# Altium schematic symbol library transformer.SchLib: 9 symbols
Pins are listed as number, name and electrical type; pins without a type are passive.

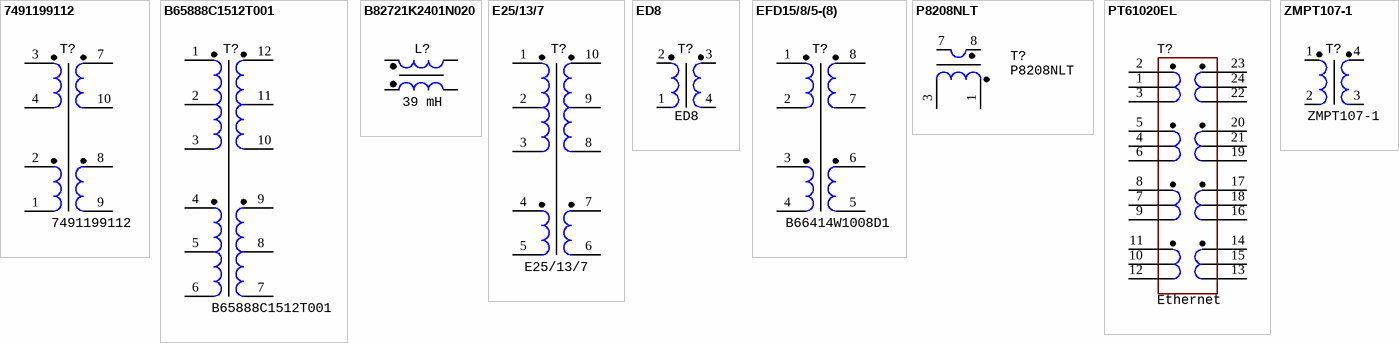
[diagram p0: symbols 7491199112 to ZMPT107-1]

## 7491199112
designator T?
PoE, EP13, 36...57V, output 12V, 13W, 550 mA, 200...500 kHz, 127 uH, -40...+125°C
footprint TRANS: EP13 (7491199112)
pins: 1 (power), 2 (power), 3 (power), 4 (power), 7 (power), 8 (power), 9 (power), 10 (power)

## B65888C1512T001
designator T?
RM14, 12 pins, 40...+125°C; Manufacture: Epcos
footprint TRANS: RM14 (TR V.1)
pins: 1 (power), 2 (power), 3 (power), 4 (power), 5 (power), 6 (power), 7 (power), 8 (power), 9 (power), 10 (power), 11 (power), 12 (power)

## B82721K2401N020
designator L?  value 39 mH  (hidden comment: B82721K2401N020)
EMI filter, 39 mH, 400 mA, 2 Ohms, -40...+125°C; Manufacture: Epcos
footprint IND: B82721
pins: 1, 2, 3, 4

## E25/13/7
designator T?
E25 vertical, 10 pins, -40...+125°C; PartNumber: B66208W1010T001; Manufacture: Epcos
footprint TRANS: E25/13/7
pins: 1 (power), 2 (power), 3 (power), 4 (power), 5 (power), 6 (power), 7 (power), 8 (power), 9 (power), 10 (power)

## ED8
designator T?
Audio transformer, 600:600 Ohms, 1.2 uH, -40...+70°C; Manufacture: Qingxian Zeming
footprint TRANS: ED8
pins: 1 (power), 2 (power), 3 (power), 4 (power)

## EFD15/8/5-(8)
designator T?  PartNumber: B66414W1008D1  (hidden comment: EFD15/8/5-(8))
EFD25 horizontal, 8 pins, -40...+125°C; Manufacture: Epcos
footprint TRANS: EFD15/8/5 - (8)
pins: 1 (power), 2 (power), 3 (power), 4 (power), 5 (power), 6 (power), 7 (power), 8 (power)

## P8208NLT
designator T?
Current sensor, 10A, 50...1000 kHz, 1:100, -40...+125°C; Manufacture: Pulse Electronics
footprint TRANS: P8208NLT
pins: 1 (power), 3 (power), 7 (power), 8 (power)

## PT61020EL
designator T?  Package: Ethernet  (hidden comment: PT61020EL)
Ethernet, 10/100/1000 Base-T, 4 pairs, 1500 Vrms, -40...+85°C; Manufacturer: Bourns
footprint TRANS: 749020011A (Transformer Ethernet) (1G Ethernet transformer)
pins: 1 (power), 2 (power), 3, 4, 5, 6, 7, 8, 9, 10, 11, 12, 13, 14, 15, 16, 17, 18, 19, 20, 21, 22, 23, 24

## ZMPT107-1
designator T?
Voltage sensor, 1000V, 2mA, 3000 Vrms, 0.6%, -40...+70°C; Manufacture: Qingxian Zeming
footprint TRANS: ZMPT107-1 (Voltage Transformer)
pins: 1 (power), 2 (power), 3 (power), 4 (power)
